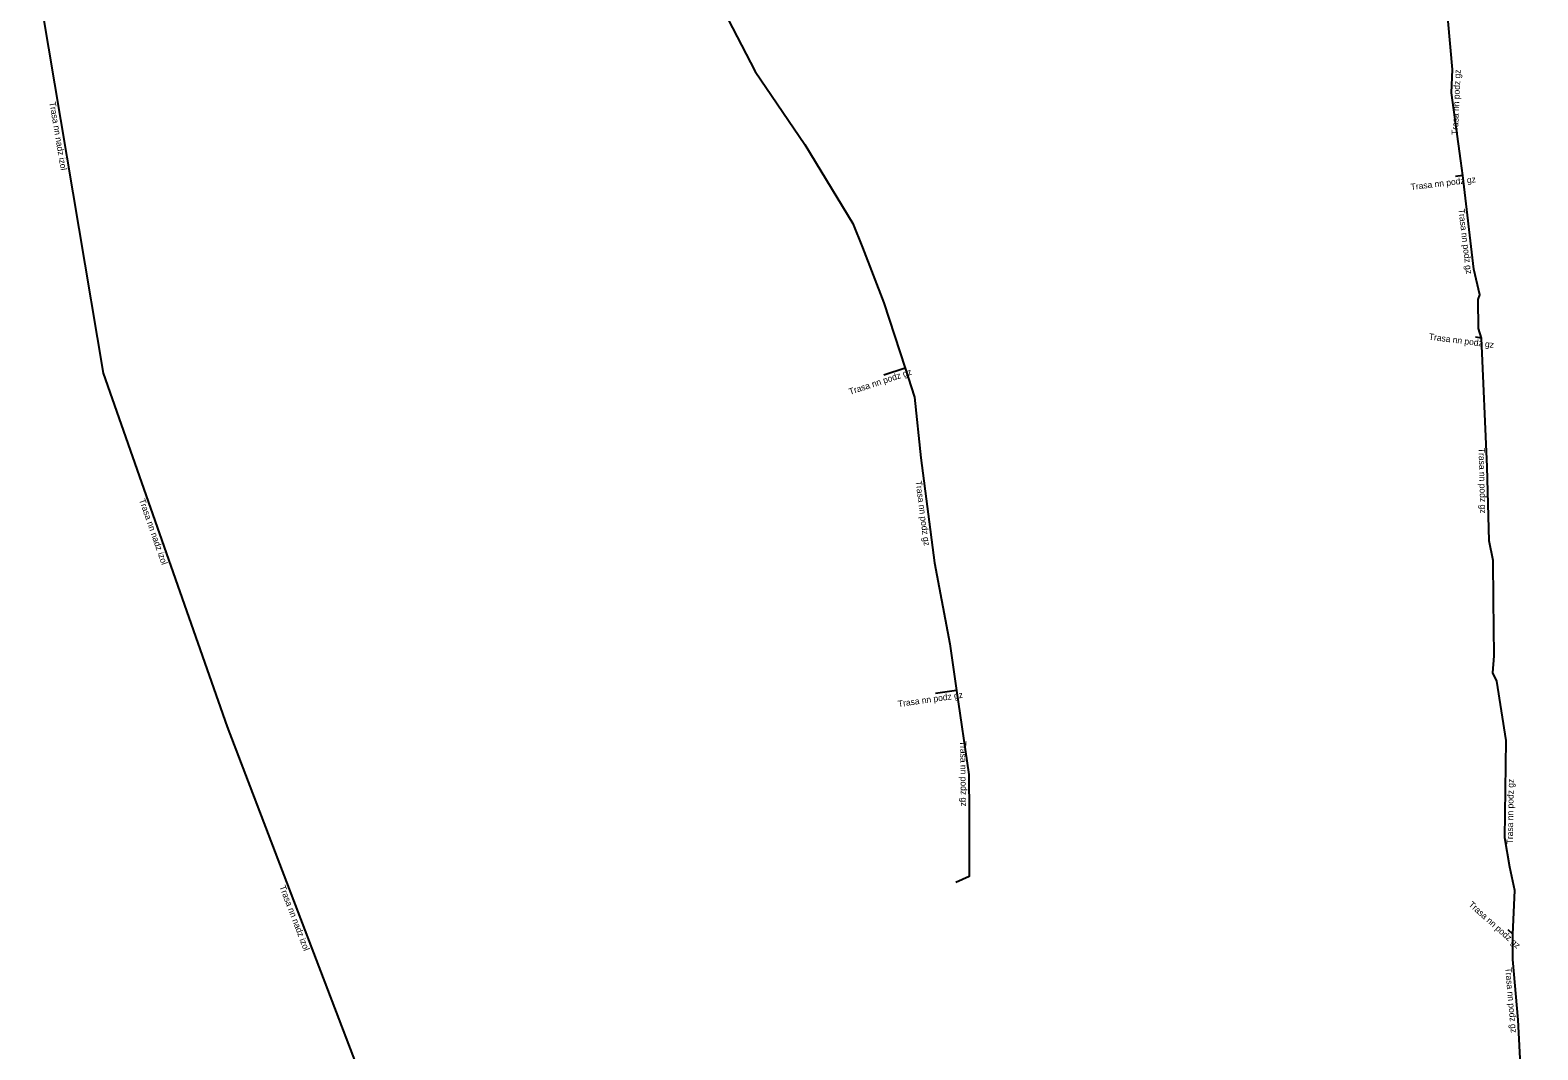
# Model space of a CAD drawing. Extents: x -745887 to -745704, y -1028211 to -1027575.
# Drawn here: x -745885.2 to -745766.3, y -1027891.8 to -1027811.5 of the extents above; entities that cross this region are included whole.
import ezdxf

# ---------------------------------------------------------------- set-up
doc = ezdxf.new("R2010")
doc.units = 0
doc.layers.add('Popiskový text - Ostatní atributy Trasy', color=7, linetype='Continuous')
doc.layers.add('Spojnice NN', color=7, linetype='Continuous')

msp = doc.modelspace()

# ---------------------------------------------------------------- linework, layer by layer
at = {"layer": 'Spojnice NN'}
for points in [[(-745854.57, -1027760.54), (-745852.79, -1027763.06), (-745848.43, -1027772.78), (-745844.64, -1027781.81), (-745841.31, -1027788.98), (-745837.53, -1027796.88), (-745832.04, -1027807.15), (-745830.5, -1027809.94), (-745828.02, -1027814.74), (-745824.1, -1027820.51), (-745820.33, -1027826.73), (-745819.57, -1027828.63), (-745817.89, -1027832.97), (-745816.2, -1027838.12)], [(-745885.15, -1027804.31), (-745879.39, -1027838.51)], [(-745772.26, -1027822.95), (-745772.4, -1027821.8), (-745773.14, -1027816.42), (-745773.06, -1027814.59), (-745773.59, -1027808.7)], [(-745772.26, -1027822.95), (-745772.82, -1027823.02)], [(-745770.77, -1027835.75), (-745771.01, -1027835), (-745771.04, -1027832.71), (-745770.9, -1027832.35), (-745771.38, -1027830.32), (-745772.26, -1027822.95)], [(-745770.77, -1027835.75), (-745771.25, -1027835.69)], [(-745769.77, -1027860.79), (-745769.83, -1027856.37), (-745769.85, -1027853.29), (-745770.17, -1027851.74), (-745770.32, -1027845.89), (-745770.77, -1027835.75)], [(-745879.39, -1027838.51), (-745869.63, -1027866.37)], [(-745816.2, -1027838.12), (-745817.89, -1027838.67)], [(-745816.2, -1027838.12), (-745815.45, -1027840.41), (-745814.96, -1027845.19), (-745813.89, -1027853.45), (-745812.68, -1027859.85), (-745812.15, -1027863.51)], [(-745768.32, -1027882.72), (-745768.14, -1027879.29), (-745768.55, -1027877.44), (-745768.95, -1027875.13), (-745768.9, -1027871.34), (-745768.84, -1027867.46), (-745769.58, -1027862.79), (-745769.88, -1027862.12), (-745769.77, -1027860.79)], [(-745812.15, -1027863.51), (-745813.8, -1027863.75)], [(-745812.15, -1027863.51), (-745811.18, -1027870.15), (-745811.14, -1027873.22), (-745811.16, -1027878.17), (-745812.2, -1027878.65)], [(-745869.63, -1027866.37), (-745857.05, -1027899.32)], [(-745768.32, -1027882.72), (-745768.69, -1027882.39)], [(-745766.34, -1027895.2), (-745767.69, -1027893.53), (-745767.9, -1027889.46), (-745768.31, -1027884.72), (-745768.32, -1027882.72)]]:
    msp.add_lwpolyline(points, dxfattribs=at)

# ---------------------------------------------------------------- texts
at = {"layer": 'Popiskový text - Ostatní atributy Trasy'}
for s, rotation, p in [('Trasa nn podz gz', 87.4982, (-745772.64, -1027819.76)), ('Trasa nn nadz izol', 279.5644, (-745883.64, -1027817.18)), ('Trasa nn podz gz', 6.948, (-745776.33, -1027824.1)), ('Trasa nn podz gz', 276.8501, (-745772.6, -1027825.6)), ('Trasa nn podz gz', 352.614, (-745774.95, -1027835.87)), ('Trasa nn podz gz', 18.1899, (-745820.54, -1027840.23)), ('Trasa nn podz gz', 271.5291, (-745771.01, -1027844.41)), ('Trasa nn podz gz', 277.4409, (-745815.38, -1027847.03)), ('Trasa nn nadz izol', 289.2961, (-745876.58, -1027848.51)), ('Trasa nn podz gz', 8.237, (-745816.73, -1027864.83)), ('Trasa nn podz gz', 270.8398, (-745811.87, -1027867.49)), ('Trasa nn podz gz', 89.123, (-745768.31, -1027875.64)), ('Trasa nn nadz izol', 290.9007, (-745865.52, -1027878.98)), ('Trasa nn podz gz', 318.2705, (-745771.84, -1027880.45)), ('Trasa nn podz gz', 275.0439, (-745768.91, -1027885.37))]:
    msp.add_text(s, height=0.5, rotation=rotation, dxfattribs=at).set_placement(p)

doc.saveas('drawing.dxf')
